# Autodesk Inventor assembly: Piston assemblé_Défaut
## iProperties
Shininess: 64.0
Length Units: 11269
Angle Units: 11279
Time Units: 11290
Mass Units: 11283
Length Display Precision: 3
Angle Display Precision: 2
Compacted: True
Created: 2006-01
Part Number: Piston assemblé_Défaut
Document SubType Name: Assembly
Designer: riri
Density: 0.0
Volumn: 0.0
Area: 0.0
PropertySet Name: Model Information
Control State: 0
Master: False
Checked Out: False
Author: riri
